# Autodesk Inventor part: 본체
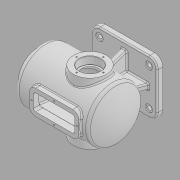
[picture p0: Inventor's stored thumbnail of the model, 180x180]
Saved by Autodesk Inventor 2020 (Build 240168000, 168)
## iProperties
Created: 2021-11
Part Number: 본체
Material: 일반
Document SubType Name: Modeling
Designer: Administrator
Density: 1 g/cm^3
Appearance: 기본값
Author: Administrator
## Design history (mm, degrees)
sketch "스케치1"
  geometry: L1 (-80, -65)-(80, -65); L2 (80, -65)-(80, 65); L3 (80, 65)-(-80, 65); L4 (-80, 65)-(-80, -65); L5 (-80, -65)-(80, 65); L6 (80, -65)-(-80, 65); 1 further point
  constraints: 12 end point, 2 midpoint, 2 parallel, 1 horizontal, 1 perpendicular
  dimensions: "d0" = 160 distance of L2.end L3.end; "d1" = 130 distance of L1.end L2.end
extrude "돌출1" new body sketch "스케치1" distance "d2" = 14; taper "d3" = 0 deg
sketch "스케치2"
  geometry: L1 (110, 114)-(-100, 114); L2 (110, 114)-(110, 161.5); L3 (110, 161.5)-(100, 161.5); L4 (100, 161.5)-(100, 179); L5 (100, 179)-(-75.993, 179); L6 (110, 114)-(110, 66.5); L7 (110, 66.5)-(100, 66.5); L8 (100, 66.5)-(100, 49); L9 (100, 49)-(-75.993, 49); L10 (80, 0)-(80, 14) reference; L11 (90, 146.5)-(90, 169); L12 (90, 169)-(-71.239, 169); L13 (90, 146.5)-(110, 146.5); A1 r 100 centre (0, 114) between (-75.993, 179) and (-75.993, 49); A2 r 90 centre (0, 114) between (-71.239, 169) and (-71.239, 59); 2 further points
  constraints: 24 end point, 5 point on circle, 4 perpendicular, 4 symmetric about line, 2 centre point, 2 horizontal, 1 point on line, 1 vertical, 2 other
  dimensions: "d4" = 114 vertical distance of point (0, 0) L1.start; "d5" = 100 radius of A1; "d6" = 210 distance from line of L1.end L2; "d7" = 130 distance between parallel lines of L9 L5; "d8" = 95 distance between parallel lines of L7 L3; "d9" = 30 distance between parallel lines of L10 L6; "d10" = 10 distance of L2.end L3.end; "d11" = 10 radial gap between concentric circles of A1 A2; "d80" = 65 diameter of L13 L1
revolve "회전1" sketch "스케치2" stored, may be unused: angle "d12" = 90 deg
sketch "스케치3"
  geometry: L1 (-7, -7)-(7, -7); L2 (7, -7)-(7, 7); L3 (7, 7)-(-7, 7); L4 (-7, 7)-(-7, -7); L5 (-7, -7)-(7, 7); L6 (7, -7)-(-7, 7); 1 further point
  constraints: 12 end point, 2 midpoint, 2 parallel, 1 horizontal, 1 perpendicular
  dimensions: "d13" = 14 distance of L3.end L2.end; "d14" = 14 distance of L2.end L1.end
extrude "돌출2" join sketch "스케치3" stored distance "d15" = 14; taper "d16" = 0 deg
sketch "스케치4"
  geometry: L1 (-75.993, 49)-(100, 49) reference; L2 (-80, 14)-(80, 14) reference; L3 (60, 14)-(47.261, 49); 1 further point
  constraints: 2 end point, 2 point on line
  dimensions: "d18" = 60 horizontal distance of L3.start point (0, 0); "d19" = 110 deg angle of L2 L3
feature "리브1" sketch "스케치4" dims "d20" = 1, "d21" = 14, "d22" = 0, "d23" = 0, "d24" = 1, "d25" = 1
sketch "스케치5"
  geometry: L1 (65, 14)-(-65, 14) reference; L2 (-50, 14)-(-33.809, 58.485); 2 further points
  constraints: 2 end point, 1 point on line, 2 other
  dimensions: "d26" = 50 horizontal distance of L2.start point (0, 0); "d27" = 110 deg angle of L1 L2
feature "리브2" sketch "스케치5" dims "d28" = 1, "d29" = 14, "d30" = 0, "d31" = 0, "d32" = 1, "d33" = 1
node "작업 평면1"
sketch "스케치6"
  geometry: L1 (110, 66.5)-(110, 161.5) reference; C1 r 40 at (-17, 114); 2 further points
  constraints: 1 centre point, 1 horizontal alignment, 1 midpoint
  dimensions: "d35" = 127 distance from line of L1 C1.centre; "d36" = 80 diameter of C1
extrude "돌출3" join sketch "스케치6" stored distance "d37" = 14; taper "d38" = 0 deg
sketch "스케치7"
  geometry: C1 r 40 at (0, 0) reference; 2 further points
  constraints: 1 coincident
hole "구멍1" sketch "스케치7" at (0, 0) diameter "d39" = 42; stored, may be unused: countersink angle "d43" = 90 deg, drill point angle "d45" = 118 deg; dims "d40" = 8, "d41" = 52, "d42" = 18, "d44" = 10
sketch "스케치8" dims "d46" = 65
  geometry: L1 (0, 0)-(0, -32.5); C1 r 26 at (0, 0) reference; 2 further points
  constraints: 2 coincident, 2 end point, 1 vertical, 1 vertical alignment, 2 other
hole "구멍2" sketch "스케치8" at (0, -32.5) diameter "d47" = 3.45873; stored, may be unused: countersink angle "d51" = 90 deg, drill point angle "d53" = 118 deg; dims "d48" = 11, "d49" = 52, "d50" = 18, "d52" = 13
node "작업 평면2"
sketch "스케치9"
  geometry: L1 (-60, 30)-(60, 30); L2 (60, 30)-(60, -30); L3 (60, -30)-(-60, -30); L4 (-60, -30)-(-60, 30); L5 (-110, 47.5)-(-110, -47.5) reference; 2 further points
  constraints: 8 end point, 2 parallel, 1 horizontal, 1 horizontal alignment, 1 midpoint, 1 perpendicular
  dimensions: "d58" = 50 distance between parallel lines of L4 L5; "d59" = 120 distance of L1.start L1.end; "d60" = 60 distance of L1.end L2.end
extrude "돌출4" join sketch "스케치9" stored distance "d61" = 14; taper "d62" = 0 deg
sketch "스케치10"
  geometry: L1 (-60, -30)-(60, -30) reference; L2 (60, -30)-(60, 30) reference; L3 (60, 30)-(-60, 30) reference; L4 (-60, 30)-(-60, -30) reference; L5 (-50, 20)-(50, 20); L6 (50, 20)-(50, -20); L7 (50, -20)-(-50, -20); L8 (-50, -20)-(-50, 20); 1 further point
  constraints: 8 end point, 3 other
  dimensions: "d63" = 10 distance between parallel lines of L3 L5
extrude "돌출5" cut sketch "스케치10" stored distance "d64" = 14; taper "d65" = 0 deg
fillet "모깎기1" dims "d66" = 15
fillet "모깎기2" dims "d67" = 5
sketch "스케치11"
  geometry: 5 further points
  constraints: 2 horizontal alignment, 2 vertical alignment
  dimensions: "d68" = 50 distance of point (0, -25) point (0, 25); "d69" = 25 distance of point (0, 0) point (0, 25); "d70" = 55 distance of point (0, 0) point (-55, 0); "d71" = 55 distance of point (55, 0) point (0, 0)
hole "구멍3" sketch "스케치11" at (0, 25), (-55, 0), (55, 0), (0, -25) diameter "d72" = 3.45873; stored, may be unused: countersink angle "d76" = 90 deg, drill point angle "d78" = 118 deg; dims "d73" = 9, "d74" = 52, "d75" = 18, "d77" = 11
sketch "스케치13" dims "d81" = 80
  geometry: L1 (0, 0)-(40, 0); C1 r 47.5 at (0, 0) reference; C2 r 32.5 at (0, 0) reference; 2 further points
  constraints: 2 coincident, 2 end point, 1 horizontal, 1 horizontal alignment, 2 other
hole "구멍4" sketch "스케치13" at (40, 0) diameter "d82" = 3.45873; stored, may be unused: countersink angle "d86" = 90 deg, drill point angle "d88" = 118 deg; dims "d83" = 11, "d84" = 52, "d85" = 18, "d87" = 13
fillet "모깎기3" dims "d92" = 10
fillet "모깎기4" dims "d93" = 10
fillet "모깎기5" dims "d94" = 3
fillet "모깎기6" dims "d95" = 3
fillet "모깎기7" dims "d96" = 3
fillet "모깎기8" dims "d97" = 3
fillet "모깎기9" dims "d98" = 20
sketch "스케치14"
  geometry: L1 (-80, 45)-(-80, -45) reference; L2 (60, 65)-(-60, 65) reference; L3 (80, -45)-(80, 45) reference; L4 (-60, -65)-(60, -65) reference; A1 r 20 centre (-60, -45) between (-80, -45) and (-60, -65) reference; A2 r 20 centre (-60, 45) between (-60, 65) and (-80, 45) reference; A3 r 20 centre (60, 45) between (80, 45) and (60, 65) reference; A4 r 20 centre (60, -45) between (60, -65) and (80, -45) reference; 5 further points
  constraints: 4 coincident
hole "구멍5" sketch "스케치14" at (60, -45), (-60, -45), (60, 45), (-60, 45) diameter "d99" = 9; stored, may be unused: countersink angle "d103" = 90 deg, drill point angle "d105" = 118 deg; dims "d100" = 11, "d101" = 18, "d102" = 2, "d104" = 13
fillet "모깎기10" dims "d106" = 3
fillet "모깎기11" dims "d107" = 3
chamfer "모따기1" distance "d108" = 1; stored, may be unused: second distance "d109" = 2, angle "d110" = 45 deg
fillet "모깎기12" dims "d111" = 3
sketch "스케치15"
  geometry: L1 (0, 0)-(120, 0) reference; L2 (39.261, 8.002)-(80.739, 8.002); L3 (80.739, 8.002)-(80.739, 1.998); L4 (80.739, 1.998)-(39.261, 1.998); L5 (39.261, 1.998)-(39.261, 8.002); L6 (39.261, 8.002)-(80.739, 1.998); L7 (80.739, 8.002)-(39.261, 1.998); 4 further points
  constraints: 4 end point, 3 midpoint, 1 vertical alignment, 2 other
  dimensions: "d112" = 5 distance of point (60, 5) point (60, 0)
feature "엠보싱1" sketch "스케치15" dims "d113" = 0.5, "d114" = 0
chamfer "모따기2" distance "d115" = 1; stored, may be unused: second distance "d116" = 2, angle "d117" = 45 deg
fillet "모깎기13" dims "d118" = 0.3
node "솔리드1"
mirror "미러1"
mirror "미러2"
mirror "미러3"
mirror "미러4"
pattern_circular "원형 패턴1" dims angle "d55" = 360 deg
mirror "미러5"
pattern_circular "원형 패턴2" dims angle "d90" = 360 deg
node "투영된 루프1"
node "투영된 루프2"
node "투영된 루프3"
feature "A9D066F2-1C7D-4E18-AEED-F7BC21143FA4" dims "d39" = 42, "d40" = 8, "d41" = 52, "d42" = 18, "d43" = 90 deg, "d44" = 10, "d45" = 118 deg
other parameters: "d34" = 75, "d57" = 184
